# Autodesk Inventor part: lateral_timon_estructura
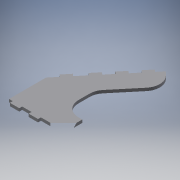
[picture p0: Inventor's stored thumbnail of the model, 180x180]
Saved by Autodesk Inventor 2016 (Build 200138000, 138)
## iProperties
Created: 2017-06
Part Number: lateral_timon_estructura
Material: Generic
Document SubType Name: Modeling
Designer: laboratorioesan
Density: 1 g/cm^3
Appearance: Default
Author: laboratorioesan
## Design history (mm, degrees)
sketch "Sketch1"
  geometry: L1 (0, 0)-(32.036, 38.389) reference; L2 (0, 0)-(11.901, -9.931) reference; L3 (43.937, 28.458)-(11.901, -9.931) reference; L4 (32.036, 38.389)-(43.937, 28.458) reference; L5 (-64.072, -76.777)-(-32.036, -38.389) reference; L6 (-64.072, -76.777)-(-52.172, -86.709) reference; L7 (-20.136, -48.32)-(-52.172, -86.709) reference; L8 (-32.036, -38.389)-(-20.136, -48.32) reference; L9 (-128.144, -153.555)-(-96.108, -115.166) reference; L10 (-128.144, -153.555)-(-116.244, -163.486) reference; L11 (-84.208, -125.097)-(-116.244, -163.486) reference; L12 (-96.108, -115.166)-(-84.208, -125.097) reference; L13 (-198.623, -238.01)-(-166.587, -199.621) reference; L14 (-198.623, -238.01)-(-186.723, -247.941) reference; L15 (-154.687, -209.552)-(-186.723, -247.941) reference; L16 (-166.587, -199.621)-(-154.687, -209.552) reference; L17 (-0.435, -485.534)-(49.565, -485.534) reference; L18 (-0.435, -485.534)-(-0.435, -501.034) reference; L19 (49.565, -501.034)-(-0.435, -501.034) reference; L20 (49.565, -485.534)-(49.565, -501.034) reference; L21 (-100.435, -485.534)-(-50.435, -485.534) reference; L22 (-100.435, -485.534)-(-100.435, -501.034) reference; L23 (-50.435, -501.034)-(-100.435, -501.034) reference; L24 (-50.435, -485.534)-(-50.435, -501.034) reference; L25 (-200.44, -485.534)-(-150.44, -485.534) reference; L26 (-200.44, -485.534)-(-200.44, -501.034) reference; L27 (-150.44, -501.034)-(-200.44, -501.034) reference; L28 (-150.44, -485.534)-(-150.44, -501.034) reference; L29 (-220.44, -485.534)-(69.565, -485.534); L30 (69.565, -485.534)-(69.565, 59.169); L31 (69.565, 59.169)-(-220.44, -288.345); L32 (-220.44, -288.345)-(-220.44, -485.534)
  constraints: 8 end point, 1 collinear, 1 horizontal, 1 parallel, 1 perpendicular, 1 point on line
  dimensions: "d0" = 20 distance of L25.start L29.start; "d1" = 20 distance of L29.end L17.end
extrude "Extrusion1" new body sketch "Sketch1" distance "d2" = 15.5; taper "d3" = 0 deg
sketch "Sketch2"
  geometry: L1 (-96.108, -115.166)-(-128.144, -153.555) reference; L2 (-128.144, -153.555)-(-116.244, -163.486) reference; L3 (-116.244, -163.486)-(-154.687, -209.552) reference; L4 (-154.687, -209.552)-(-166.587, -199.621) reference; L5 (-166.587, -199.621)-(-198.623, -238.01) reference; L6 (-198.623, -238.01)-(-186.723, -247.941) reference; L7 (-186.723, -247.941)-(-220.44, -288.345) reference; L8 (-220.44, -288.345)-(-220.44, -485.534) reference; L9 (-220.44, -485.534)-(69.565, -485.534) reference; L10 (69.565, -485.534)-(69.565, 59.169) reference; L11 (69.565, 59.169)-(43.937, 28.458) reference; L12 (43.937, 28.458)-(32.036, 38.389) reference; L13 (32.036, 38.389)-(0, 0) reference; L14 (0, 0)-(11.901, -9.931) reference; L15 (11.901, -9.931)-(-20.136, -48.32) reference; L16 (-20.136, -48.32)-(-32.036, -38.389) reference; L17 (-32.036, -38.389)-(-64.072, -76.777) reference; L18 (-64.072, -76.777)-(-52.172, -86.709) reference; L19 (-52.172, -86.709)-(-84.208, -125.097) reference; L20 (-84.208, -125.097)-(-96.108, -115.166) reference; L21 (69.565, -485.534)-(69.565, 59.169) reference; L22 (69.565, -96.906)-(-30.435, -216.736); L23 (-30.435, -216.736)-(-30.435, -385.534); L24 (-30.435, -385.534)-(69.565, -385.534); 1 further point
  constraints: 6 end point, 2 parallel, 2 point on line, 1 perpendicular
  dimensions: "d4" = 100 distance between parallel lines of L9 L24; "d5" = 100 distance between parallel lines of L19 L22; "d6" = 100 distance between parallel lines of L10 L23
extrude "Extrusion2" cut sketch "Sketch2" distance "d7" = 15.5; taper "d8" = 0 deg
sketch "Sketch3"
  geometry: L1 (-50.435, -485.534)-(-100.435, -485.534) reference; L2 (-50.435, -485.534)-(-50.435, -501.034) reference; L3 (-100.435, -501.034)-(-50.435, -501.034) reference; L4 (-100.435, -485.534)-(-100.435, -501.034) reference; L5 (49.565, -485.534)-(-0.435, -485.534) reference; L6 (49.565, -485.534)-(49.565, -501.034) reference; L7 (-0.435, -501.034)-(49.565, -501.034) reference; L8 (-0.435, -485.534)-(-0.435, -501.034) reference; L9 (-150.44, -485.534)-(-200.44, -485.534) reference; L10 (-150.44, -485.534)-(-150.44, -501.034) reference; L11 (-200.44, -501.034)-(-150.44, -501.034) reference; L12 (-200.44, -485.534)-(-200.44, -501.034) reference; 1 further point
extrude "Extrusion3" join sketch "Sketch3" distance "d9" = 15.5; taper "d10" = 0 deg
fillet "Fillet1" dims "d11" = 80
fillet "Fillet2" dims "d12" = 80
fillet "Fillet3" dims "d13" = 80
sketch "Sketch4"
  geometry: L1 (69.565, -67.91)-(69.565, 59.169) reference; L2 (69.565, 59.169)-(43.937, 28.458) reference; L3 (43.937, 28.458)-(32.036, 38.389) reference; L4 (32.036, 38.389)-(0, 0) reference; L5 (0, 0)-(11.901, -9.931) reference; L6 (11.901, -9.931)-(-20.136, -48.32) reference; L7 (-20.136, -48.32)-(-32.036, -38.389) reference; L8 (-32.036, -38.389)-(-64.072, -76.777) reference; L9 (-64.072, -76.777)-(-52.172, -86.709) reference; L10 (-52.172, -86.709)-(-84.208, -125.097) reference; L11 (-84.208, -125.097)-(-96.108, -115.166) reference; L12 (-96.108, -115.166)-(-128.144, -153.555) reference; L13 (-128.144, -153.555)-(-116.244, -163.486) reference; L14 (-116.244, -163.486)-(-154.687, -209.552) reference; L15 (-154.687, -209.552)-(-166.587, -199.621) reference; L16 (-166.587, -199.621)-(-198.623, -238.01) reference; L17 (-198.623, -238.01)-(-186.723, -247.941) reference; L18 (-186.723, -247.941)-(-220.44, -288.345) reference; L19 (-220.44, -288.345)-(-220.44, -485.534) reference; L20 (-220.44, -485.534)-(-200.44, -485.534) reference; L21 (-200.44, -485.534)-(-200.44, -501.034) reference; L22 (-200.44, -501.034)-(-150.44, -501.034) reference; L23 (-150.44, -501.034)-(-150.44, -485.534) reference; L24 (-150.44, -485.534)-(-100.435, -485.534) reference; L25 (-100.435, -485.534)-(-100.435, -501.034) reference; L26 (-100.435, -501.034)-(-50.435, -501.034) reference; L27 (-50.435, -501.034)-(-50.435, -485.534) reference; L28 (-50.435, -485.534)-(-0.435, -485.534) reference; L29 (-0.435, -485.534)-(-0.435, -501.034) reference; L30 (-0.435, -501.034)-(49.565, -501.034) reference; L31 (49.565, -501.034)-(49.565, -485.534) reference; L32 (49.565, -485.534)-(69.565, -485.534) reference; L33 (69.565, -485.534)-(69.565, -385.534) reference; L34 (69.565, -385.534)-(49.565, -385.534) reference; L35 (-30.435, -305.534)-(-30.435, -245.731) reference; L36 (-11.857, -194.474)-(50.987, -119.168) reference; L37 (69.565, 59.169)-(142.147, -9.931); L38 (142.147, -9.931)-(24.606, -150.781); A1 r 80 centre (-10.435, -67.91) between (50.987, -119.168) and (69.565, -67.91) reference; A2 r 80 centre (49.565, -305.534) between (-30.435, -305.534) and (49.565, -385.534) reference; A3 r 80 centre (49.565, -245.731) between (-11.857, -194.474) and (-30.435, -245.731) reference; 1 further point
  constraints: 4 end point, 1 point on line
extrude "Extrusion4" join sketch "Sketch4" distance "d14" = 15.5; taper "d15" = 0 deg
fillet "Fillet4" dims "d16" = 80
body "Solid1"
node "Reference1"
node "Reference2"
node "Reference3"
node "Reference4"
node "Reference5"
node "Reference6"
node "Reference7"
node "Reference8"
node "Projected Loop1"
node "Reference9"
node "Reference10"
node "Reference11"
node "Projected Loop2"
